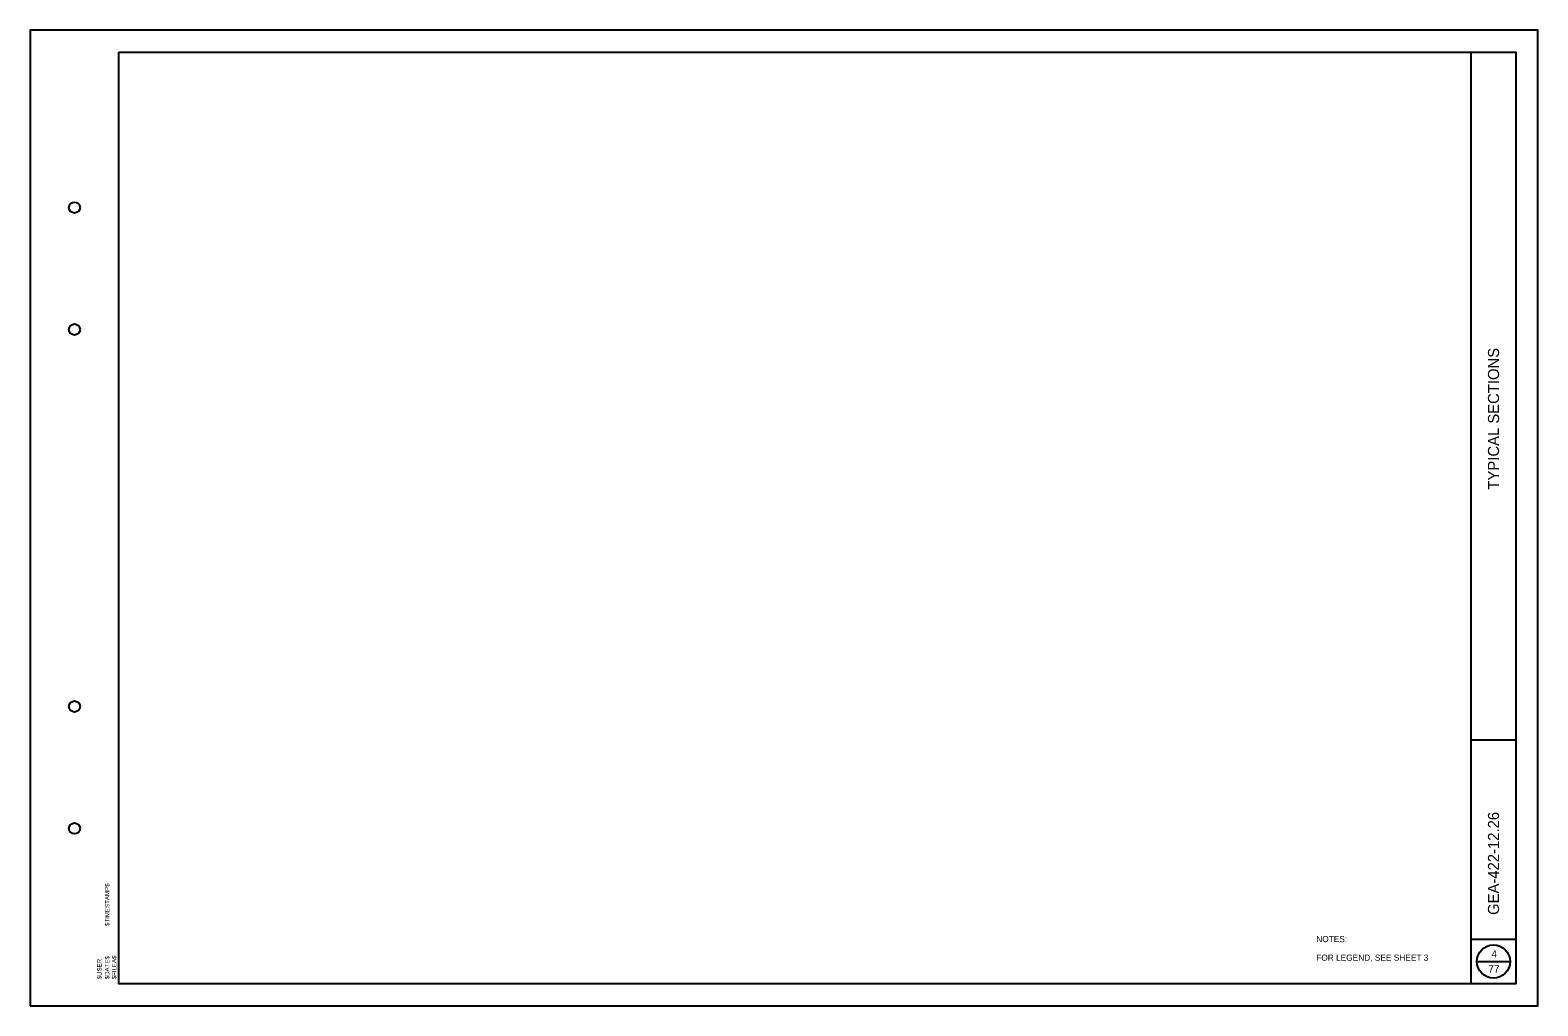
# Model space of a CAD drawing. Extents: x 0 to 34, y 0 to 22.
import ezdxf

# ---------------------------------------------------------------- set-up
doc = ezdxf.new("R2010")
doc.units = 0
for name, color, linetype in [('SH_Border', 7, 'Continuous'), ('SH_Cut_Line', 7, 'Continuous'), ('SH_Data', 7, 'Continuous'), ('SH_Text', 7, 'Continuous')]:
    doc.layers.add(name, color=color, linetype=linetype)

msp = doc.modelspace()

# ---------------------------------------------------------------- linework, layer by layer
at = {"layer": 'SH_Border'}
for p, q in [((32.5, 0.5), (32.5, 21.5)), ((32.5, 6), (33.5, 6)), ((32.5, 1.5), (33.5, 1.5))]:
    msp.add_line(p, q, dxfattribs=at)
msp.add_lwpolyline([(2, 21.5), (33.5, 21.5), (33.5, 0.5), (2, 0.5)], close=True, dxfattribs=at)
for centre in [(1, 18), (1, 15.25), (1, 6.75), (1, 4)]:
    msp.add_circle(centre, 0.125, dxfattribs=at)
at = {"layer": 'SH_Cut_Line'}
msp.add_lwpolyline([(0, 0), (34, 0), (34, 22), (0, 22)], close=True, dxfattribs=at)
at = {"layer": 'SH_Data'}
msp.add_line((32.625, 1), (33.375, 1), dxfattribs=at)
msp.add_circle((33, 1), 0.375, dxfattribs=at)

# ---------------------------------------------------------------- texts
for s, height, rotation, p in [('TYPICAL SECTIONS', 0.25, 90, (33.125, 11.641)), (' GEA-422-12.26 ', 0.25, 90, (33.125, 1.957)), ('$TIMESTAMP$', 0.1, 89.9931, (1.788, 1.8)), ('$USER', 0.1, 89.9931, (1.611, 0.598)), ('$DATE$', 0.1, 89.9931, (1.788, 0.598)), ('$FILEA$', 0.1, 89.9931, (1.944, 0.598))]:
    msp.add_text(s, height=height, rotation=rotation, dxfattribs=at).set_placement(p)
for s, p in [('4', (32.954, 1.085)), ('77', (32.882, 0.745))]:
    msp.add_text(s, height=0.17, dxfattribs=at).set_placement(p)
at = {"layer": 'SH_Text'}
for s, p in [('NOTES:', (29.003, 1.436)), ('FOR LEGEND, SEE SHEET 3', (29.003, 1.016))]:
    msp.add_text(s, height=0.14, dxfattribs=at).set_placement(p)

doc.saveas('drawing.dxf')
